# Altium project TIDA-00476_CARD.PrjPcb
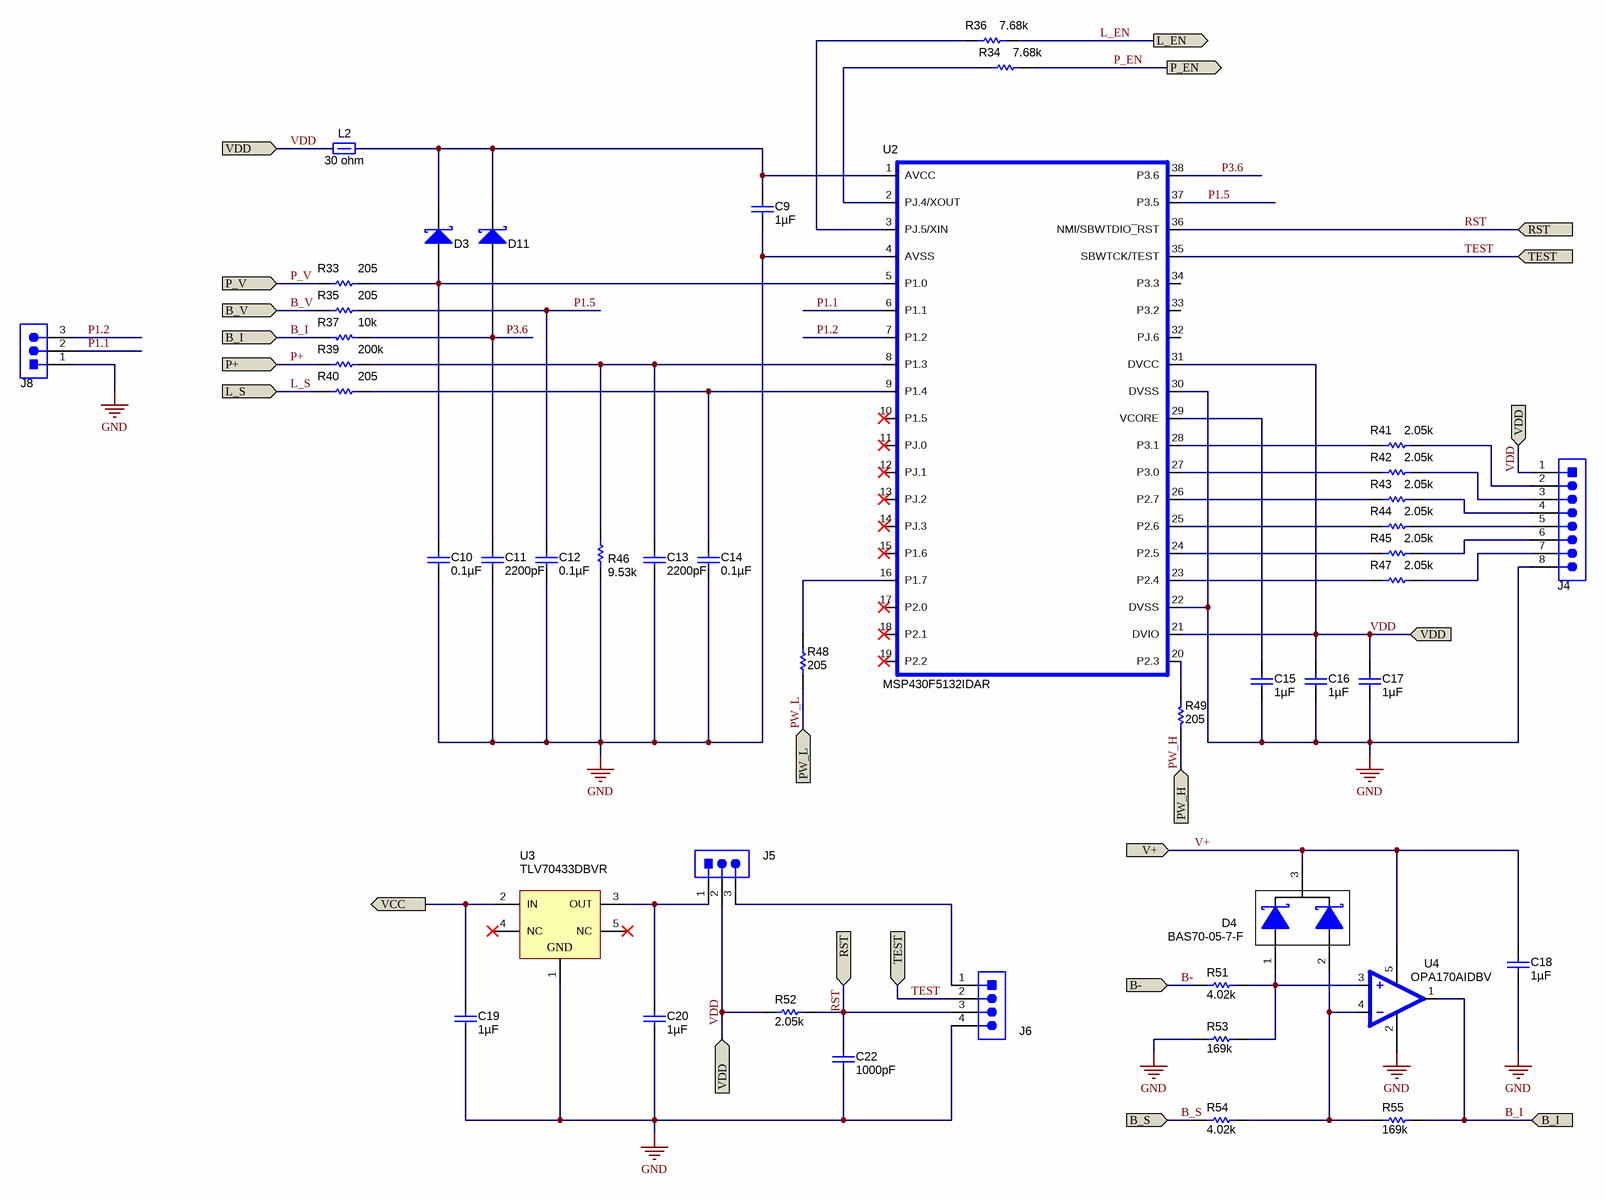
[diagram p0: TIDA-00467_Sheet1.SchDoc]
TechSupport: http://www.ti.com/support; SCH_Rev: E1; PRJ_Title: Versatile Bi-Directional Power Converter; PRJ_Number: TIDA-00476; PRJ_Engineer: Ramkumar S; PRJ_Customer: Public Release; PCB_Rev: E1; PCB_Layout: Manjunatha T N; CopyrightYear: 2015
3 sheets, 133 parts. Net scope: flat (ports and power ports of the same name join across sheets).
Board file: TIDA-00476_E1.PcbDoc
Sheets:
  TIDA-00467_Sheet1.SchDoc
  TIDA-00476_Sheet2.SchDoc
  Hardware.SchDoc

## Sheet TIDA-00467_Sheet1.SchDoc
size 431 x 279 mm; Date: Not shown in title block; ApprovedBy: Not shown in title block; CheckedBy: Not shown in title block; Author: Not shown in title block; CompanyName: Not shown in title block; Engineer: Not shown in title block; Organization: Not shown in title block; Address1: Not shown in title block; Address2: Not shown in title block; Address3: Not shown in title block; Address4: Not shown in title block; DocumentNumber: 1; Revision: Use project parameter SCH_Rev; SheetNumber: 1; SheetTotal: 3; PageSetup: Record=PageOptions¦CenterHorizontal=True¦CenterVertical=True¦PrintScale=1.00¦XCorrection=1.00¦YCorrection=1.00¦PrintKind=0¦BorderSize=5000000¦LeftOffset=0¦BottomOffset=0¦Orientation=2¦PaperLength=1000¦PaperWidth=1000¦Scale=100¦PaperSource=15¦PrintQuality=600¦MediaType=1¦DitherType=10¦PaperKind=Letter¦PrintScaleMode=1

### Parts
C9  ValueDisplayed: 1µF  [0805_HV]  (hidden comment: 08055C105KAT2A)
C10  ValueDisplayed: 0.1µF  [0805_HV]  (hidden comment: 08053C104KAT2A)
C11  ValueDisplayed: 2200pF  [0805_HV]  (hidden comment: 08055C222KAT2A)
C12  ValueDisplayed: 0.1µF  [0805_HV]  (hidden comment: 08053C104KAT2A)
C13  ValueDisplayed: 2200pF  [0805_HV]  (hidden comment: 08055C222KAT2A)
C14  ValueDisplayed: 0.1µF  [0805_HV]  (hidden comment: 08053C104KAT2A)
C15  ValueDisplayed: 1µF  [0805_HV]  (hidden comment: 08055C105KAT2A)
C16  ValueDisplayed: 1µF  [0805_HV]  (hidden comment: 08055C105KAT2A)
C17  ValueDisplayed: 1µF  [0805_HV]  (hidden comment: 08055C105KAT2A)
C18  ValueDisplayed: 1µF  [0805_HV]  (hidden comment: 08055C105KAT2A)
C19  ValueDisplayed: 1µF  [0805_HV]  (hidden comment: 08055C105KAT2A)
C20  ValueDisplayed: 1µF  [0805_HV]  (hidden comment: 08055C105KAT2A)
C22  ValueDisplayed: 1000pF  [0805_HV]  (hidden comment: 08055C102KAT2A)
D3  BAS 52-02V H6327  [SOD-523]  (value not drawn)
D4  BAS70-05-7-F  [SOT-23]
D11  BAS 52-02V H6327  [SOD-523]  (value not drawn)
J4  TSW-108-07-G-S  [TSW-108-07-G-S]  (value not drawn)
J5  5-146278-3  [TE_5-146278-3]  (value not drawn)
J6  5-146278-4  [TE_5-146278-4]  (value not drawn)
J8  5-146278-3  [TE_5-146278-3]  (value not drawn)
L2  value 30 ohm  [0805_HV]  (hidden comment: MMZ2012R300A)
R33  value 205  [0805_HV]  (hidden comment: CRCW0805205RFKEA)
R34  ValueDisplayed: 7.68k  [0805_HV]  (hidden comment: CRCW08057K68FKEA)
R35  value 205  [0805_HV]  (hidden comment: CRCW0805205RFKEA)
R36  ValueDisplayed: 7.68k  [0805_HV]  (hidden comment: CRCW08057K68FKEA)
R37  value 10k  [0805_HV]  (hidden comment: CRCW080510K0JNEA)
R39  ValueDisplayed: 200k  [0805_HV]  (hidden comment: CRCW0805200KFKEA)
R40  value 205  [0805_HV]  (hidden comment: CRCW0805205RFKEA)
R41  value 2.05k  [0805_HV]  (hidden comment: CRCW08052K05FKEA)
R42  value 2.05k  [0805_HV]  (hidden comment: CRCW08052K05FKEA)
R43  value 2.05k  [0805_HV]  (hidden comment: CRCW08052K05FKEA)
R44  value 2.05k  [0805_HV]  (hidden comment: CRCW08052K05FKEA)
R45  value 2.05k  [0805_HV]  (hidden comment: CRCW08052K05FKEA)
R46  ValueDisplayed: 9.53k  [0805_HV]  (hidden comment: CRCW08059K53FKEA)
R47  value 2.05k  [0805_HV]  (hidden comment: CRCW08052K05FKEA)
R48  value 205  [0805_HV]  (hidden comment: CRCW0805205RFKEA)
R49  value 205  [0805_HV]  (hidden comment: CRCW0805205RFKEA)
R51  ValueDisplayed: 4.02k  [0805_HV]  (hidden comment: RT0805BRD074K02L)
R52  value 2.05k  [0805_HV]  (hidden comment: CRCW08052K05FKEA)
R53  ValueDisplayed: 169k  [0805_HV]  (hidden comment: RT0805BRD07169KL)
R54  ValueDisplayed: 4.02k  [0805_HV]  (hidden comment: RT0805BRD074K02L)
R55  ValueDisplayed: 169k  [0805_HV]  (hidden comment: RT0805BRD07169KL)
U2  MSP430F5132IDAR  [DA_38P]
U3  TLV70433DBVR  [DBV0005A_N]
U4  OPA170AIDBV  [SOT23-5P]

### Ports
B- (in), B_I (in), B_S (in), B_V (in), L_EN (out), L_S (in), P+ (in), P_EN (out), P_V (in), PW_H (in), PW_L (in), RST (in), TEST (in), V+, VCC, VDD, VDD (in)

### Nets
GND: C9.2 C10.2 C11.2 C12.2 C13.2 C14.2 C15.2 C16.2 C17.2 C18.2 C19.2 C20.2 C22.2 J4.8 J6.4 J8.1 R46.1 R53.1 U2.4(AVSS) U2.22(DVSS) U2.30(DVSS) U3.1(GND) U4.2(V-)
B-: R51.1 ; port B-
B_I: R37.2 R55.2 U4.1(OUT) ; port B_I
B_S: R54.1 ; port B_S
B_V: R35.1 ; port B_V
L_EN: R36.1 ; port L_EN
L_S: R40.1 ; port L_S
P1.1: J8.2 U2.6(P1.1)
P1.2: J8.3 U2.7(P1.2)
P1.5: C12.1 R35.2 U2.37(P3.5)
P3.6: C11.1 D11.2(A) R37.1 U2.38(P3.6)
P+: R39.1 ; port P+
P_EN: R34.1 ; port P_EN
P_V: R33.1 ; port P_V
PW_H: R49.1 ; port PW_H
PW_L: R48.1 ; port PW_L
RST: C22.1 J6.3 R52.2 U2.36(NMI/SBWTDIO~{_}RST) ; port RST
TEST: J6.2 U2.35(SBWTCK/TEST) ; port TEST
V+: C18.1 D4.3(K) U4.5(V+) ; port V+
VCC: C19.1 U3.2(IN) ; port VCC
VDD: C16.1 C17.1 J4.1 J5.2 L2.1 R52.1 U2.21(DVIO) U2.31(DVCC) ; port VDD
NetC9_1: C9.1 D3.1(K) D11.1(K) L2.2 U2.1(AVCC)
NetC10_1: C10.1 D3.2(A) R33.2 U2.5(P1.0)
NetC13_1: C13.1 R39.2 R46.2 U2.8(P1.3)
NetC14_1: C14.1 R40.2 U2.9(P1.4)
NetC15_1: C15.1 U2.29(VCORE)
NetC20_1: C20.1 J5.1 U3.3(OUT)
NetD4_1: D4.1(A) R51.2 R53.2 U4.3
NetD4_2: D4.2(A) R54.2 R55.1 U4.4
NetJ4_2: J4.2 R41.2
NetJ4_3: J4.3 R42.2
NetJ4_4: J4.4 R43.2
NetJ4_5: J4.5 R44.2
NetJ4_6: J4.6 R45.2
NetJ4_7: J4.7 R47.2
NetJ5_3: J5.3 J6.1
NetR34_2: R34.2 U2.2(PJ.4/XOUT)
NetR36_2: R36.2 U2.3(PJ.5/XIN)
NetR41_1: R41.1 U2.28(P3.1)
NetR42_1: R42.1 U2.27(P3.0)
NetR43_1: R43.1 U2.26(P2.7)
NetR44_1: R44.1 U2.25(P2.6)
NetR45_1: R45.1 U2.24(P2.5)
NetR47_1: R47.1 U2.23(P2.4)
NetR48_2: R48.2 U2.16(P1.7)
NetR49_2: R49.2 U2.20(P2.3)

Not connected (* = marked no-connect by the designer): U2 10(P1.5)* 11(PJ.0)* 12(PJ.1)* 13(PJ.2)* 14(PJ.3)* 15(P1.6)* 17(P2.0)* 18(P2.1)* 19(P2.2)* 32(PJ.6) 33(P3.2) 34(P3.3); U3 4(NC)* 5(NC)*

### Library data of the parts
C9 C15-C20 = 08055C105KAT2A: CAP, CERM, 1uF, 50V, +/-10%, X7R, 0805; Manufacturer: AVX; Polarized: N; CompType: Capacitor; U/M: EA; Cap_F: 0.000001; Tolerance_%: 10; Value1: Unknown; VDC_V: 50; TaMin_C: -55; TaMax_C: 125; Cap_Case: 0805
C10 C12 C14 = 08053C104KAT2A: CAP, CERM, 0.1uF, 25V, +/-10%, X7R, 0805; Manufacturer: AVX; Polarized: N; CompType: Capacitor; U/M: EA; Cap_F: 0.0000001; Tolerance_%: 10; ESR_Ohm: 0.28; Value1: 0.28 ohm; VDC_V: 25; TaMin_C: -55; TaMax_C: 125; Cap_Case: 0805
C11 C13 = 08055C222KAT2A: CAP, CERM, 2200 pF, 50 V, +/- 10%, X7R, 0805; Manufacturer: AVX; Polarized: N; CompType: Capacitor; Value: 2200pF; U/M: EA; Cap_F: 0.0000000022; Tolerance_%: 10; ESR_ohm: 0.183; Value1: 0.183 ohm; VDC_V: 50; Value2: 50V; TaMin_C: -55; TaMax_C: 125; Cap_Case: 0805
C22 = 08055C102KAT2A: CAP, CERM, 1000 pF, 50 V, +/- 10%, X7R, 0805; Manufacturer: AVX; Polarized: N; CompType: Capacitor; Value: 1000pF; U/M: EA; Cap_F: 0.000000001; Tolerance_%: 10; ESR_ohm: 0.29; Value1: 0.29 ohm; VDC_V: 50; Value2: 50V; TaMin_C: -55; TaMax_C: 125; Cap_Case: 0805
D3 D11 = BAS 52-02V H6327: Diode, Schottky, 45 V, 0.75 A, SOD-523; Manufacturer: Infineon Technologies; U/M: EA; Vf_V: 0.6; Value: 45V; Value1: 0.75A; Value2: 0.6V; Io_A: 0.75; Vr_V: 45; TJmax_C: 150
D4 = BAS70-05-7-F: Diode, Schottky, 70 V, 0.07 A, SOT-23; Manufacturer: Diodes Inc.; SymbolCreator: a0412235; U/M: EA; Vf_V: 1.7; Value: 70V; Value1: 0.07A; Value2: 1.7V; Io_A: 0.07; Vr_V: 70
J4 = TSW-108-07-G-S: Header, TH, 100mil, 8x1, Gold plated, 230 mil above insulator; Manufacturer: Samtec; SymbolCreator: a0411947; U/M: EA
J5 J8 = 5-146278-3: Header, 100mil, 3x1, Tin, TH; Manufacturer: TE Connectivity; SymbolCreator: a0799628; U/M: EA
J6 = 5-146278-4: Header, 100mil, 4x1, Tin, TH; Manufacturer: TE Connectivity; SymbolCreator: a0412235; U/M: EA
L2 = MMZ2012R300A: Ferrite Bead, 30 ohm @ 100MHz, 1.5A, 0805; Manufacturer: TDK; Imax_A: 1.5; DCR_ohm: 0.05; Value1: 0.05 ohm; ZTyp@100MHz_Ohm: 30
R33 R35 R40 R48 R49 = CRCW0805205RFKEA: RES, 205 ohm, 1%, 0.125W, 0805; Manufacturer: Vishay-Dale; CompType: Resistor; Value_Code: 205R; Tolerance_%: 1; Power_W: 0.125; VDC_V: 150; TempCo: 100 ppm/C; EIA_Code: E96; U/M: EA
R34 R36 = CRCW08057K68FKEA: RES, 7.68 k, 1%, 0.125 W, 0805; Manufacturer: Vishay-Dale; CompType: Resistor; Value: 7.68k; Res_ohm: 7680; Value_Code: 7k68; Tolerance_%: 1; Power_W: 0.125; Value2: 0.125W; VDC_V: 150; TempCo: 100 ppm/C; EIA_Code: E96; U/M: EA
R37 = CRCW080510K0JNEA: RES, 10k ohm, 5%, 0.125W, 0805; Manufacturer: Vishay-Dale; CompType: Resistor; Res_ohm: 10000; Value_Code: 10k0; Tolerance_%: 5; Power_W: 0.125; VDC_V: 150; TempCo: 200 ppm/C; EIA_Code: E24; U/M: EA
R39 = CRCW0805200KFKEA: RES, 200 k, 1%, 0.125 W, 0805; Manufacturer: Vishay-Dale; CompType: Resistor; Value: 200k; Res_ohm: 200000; Tolerance_%: 1; Power_W: 0.125; Value2: 0.125W; VDC_V: 150; TempCo: 100 ppm/C; EIA_Code: E96; U/M: EA
R41-R45 R47 R52 = CRCW08052K05FKEA: RES, 2.05k ohm, 1%, 0.125W, 0805; Manufacturer: Vishay-Dale; CompType: Resistor; Res_ohm: 2050; Value_Code: 2k05; Tolerance_%: 1; Power_W: 0.125; VDC_V: 150; TempCo: 100 ppm/C; EIA_Code: E96; U/M: EA
R46 = CRCW08059K53FKEA: RES, 9.53 k, 1%, 0.125 W, 0805; Manufacturer: Vishay-Dale; CompType: Resistor; Value: 9.53k; Res_ohm: 9530; Value_Code: 9k53; Tolerance_%: 1; Power_W: 0.125; Value2: 0.125W; VDC_V: 150; TempCo: 100 ppm/C; EIA_Code: E96; U/M: EA
R51 R54 = RT0805BRD074K02L: RES, 4.02 k, 0.1%, 0.125 W, 0805; Manufacturer: Yageo America; CompType: Resistor; Value: 4.02k; Res_ohm: 4020; Value_Code: 4k02; Tolerance_%: 0.1; Power_W: 0.125; Value2: 0.125W; VDC_V: 150; TempCo: 25 ppm/C; EIA_Code: E192; U/M: EA
R53 R55 = RT0805BRD07169KL: RES, 169 k, 0.1%, 0.125 W, 0805; Manufacturer: Yageo America; CompType: Resistor; Value: 169k; Res_ohm: 169000; Tolerance_%: 0.1; Power_W: 0.125; Value2: 0.125W; VDC_V: 150; TempCo: 25 ppm/C; EIA_Code: E192; U/M: EA
U2 = MSP430F5132IDAR: IC, MIXED SIGNAL MICROCONTROLLER; Manufacturer: TI; Alternate Manufacturer: None; Area: 330000
U3 = TLV70433DBVR: Single Output LDO, 150 mA, Fixed 3.3 V Output, 2.5 to 24 V Input, with Ultra-Low IQ, 5-pin SOT-23 (DBV), -40 to 125 degC, Green (RoHS & no Sb/Br); Manufacturer: Texas Instruments; Alternate Manufacturer: None; Alternate PartNumber: Equivalent; Accuracy(%): 2; Fixed Output Options(V): 3.3; Iout(Max)(A): 0.15; Iq(Typ)(mA): 0.003; SubFamily: Single Channel LDO; Vdo(Typ)(mV): 400; Vin(Max)(V): 24; Vin(Min)(V): 2.5
U4 = OPA170AIDBV: IC, 36V, Single-Supply, Op Amp; Manufacturer: TI; Alternate Manufacturer: None; Area: 8700

## Sheet TIDA-00476_Sheet2.SchDoc
size 431 x 279 mm; Date: Not shown in title block; ApprovedBy: Not shown in title block; CheckedBy: Not shown in title block; Author: Not shown in title block; CompanyName: Not shown in title block; Engineer: Not shown in title block; Organization: Not shown in title block; Address1: Not shown in title block; Address2: Not shown in title block; Address3: Not shown in title block; Address4: Not shown in title block; DocumentNumber: 2; Revision: Use project parameter SCH_Rev; SheetNumber: 2; SheetTotal: 3; PageSetup: Record=PageOptions¦CenterHorizontal=True¦CenterVertical=True¦PrintScale=0.64¦XCorrection=1.00¦YCorrection=1.00¦PrintKind=0¦BorderSize=5000000¦LeftOffset=0¦BottomOffset=0¦Orientation=2¦PaperLength=1000¦PaperWidth=1000¦Scale=100¦PaperSource=15¦PrintQuality=600¦MediaType=1¦DitherType=10¦PrintScaleMode=1¦PaperKind=Letter
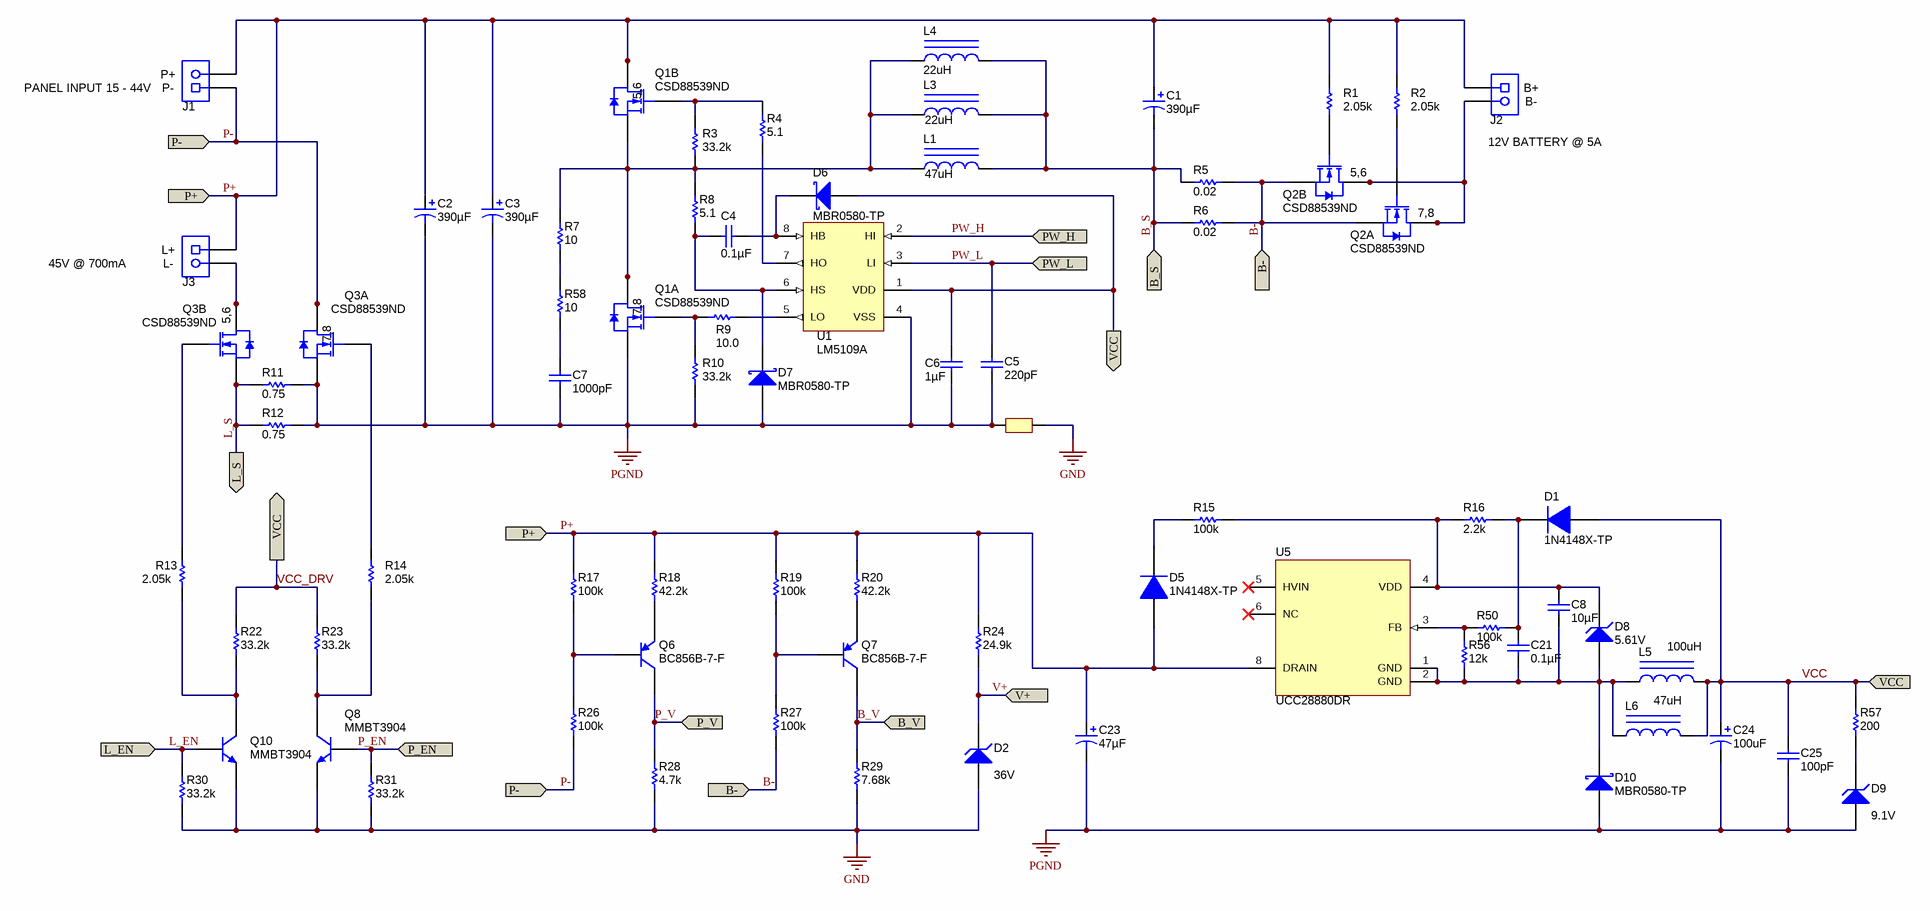
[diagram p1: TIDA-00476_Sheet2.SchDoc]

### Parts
C1  ValueDisplayed: 390µF  [KZN_1000x2000]  (hidden comment: EKYB630ELL391MJ30S)
C2  ValueDisplayed: 390µF  [KZN_1000x2000]  (hidden comment: EKYB630ELL391MJ30S)
C3  ValueDisplayed: 390µF  [KZN_1000x2000]  (hidden comment: EKYB630ELL391MJ30S)
C4  ValueDisplayed: 0.1µF  [0805_HV]  (hidden comment: 08053C104KAT2A)
C5  ValueDisplayed: 220pF  [0805_HV]  (hidden comment: GRM2165C2A221JA01D)
C6  ValueDisplayed: 1µF  [0805_HV]  (hidden comment: 08055C105KAT2A)
C7  ValueDisplayed: 1000pF  [0805_HV]  (hidden comment: GRM2195C2A102JA01D)
C8  ValueDisplayed: 10µF  [0603]  (hidden comment: C1608X5R1A106M)
C21  ValueDisplayed: 0.1µF  [0603]  (hidden comment: 0603YC104JAT2A)
C23  ValueDisplayed: 47µF  [ZLJ_500x1100]  (hidden comment: 35ZLJ47MTA5X11)
C24  ValueDisplayed: 100uF  [ZLJ_500x1100]  (hidden comment: 16PX100MEFCTA5X11)
C25  ValueDisplayed: 100pF  [0603]  (hidden comment: 06033C101KAT2A)
D1  1N4148X-TP  [SOD-523]
D2  value 36V  [SOD-123]  (hidden comment: MMSZ4715-V)
D5  1N4148X-TP  [SOD-523]
D6  MBR0580-TP  [SOD-123]
D7  MBR0580-TP  [SOD-123]
D8  5.61V  [SOD-523]
D9  value 9.1V  [SOD-123]  (hidden comment: MMSZ4696-V)
D10  MBR0580-TP  [SOD-123]
J1  282841-2  [TEC_282841-2]  (value not drawn)
J2  282841-2  [TEC_282841-2]  (value not drawn)
J3  282841-2  [TEC_282841-2]  (value not drawn)
L1  value 47uH  [WE-HCB_1890]  (hidden comment: 74435574700)
L3  value 22uH  [mss1278]  (hidden comment: MSS1278-223MLB)
L4  22uH  [WE-HCB_1890]
L5  100uH  [SRN3015]
L6  47uH  [SRN3015]
NT1  Net-Tie  [Net-Tie_20milWide_60milLong]  (value not drawn)  (net tie, no BOM)
Q1  CSD88539ND  [SO-8L]  (parts A,B of 2)
Q2  CSD88539ND  [SO-8L]  (parts A,B of 2)
Q3  CSD88539ND  [SO-8L]  (parts A,B of 2)
Q6  BC856B-7-F  [SOT-23]
Q7  BC856B-7-F  [SOT-23]
Q8  MMBT3904  [SOT-23L]
Q10  MMBT3904  [SOT-23L]
R1  value 2.05k  [0805_HV]  (hidden comment: CRCW08052K05FKEA)
R2  value 2.05k  [0805_HV]  (hidden comment: CRCW08052K05FKEA)
R3  value 33.2k  [0805_HV]  (hidden comment: CRCW080533K2FKEA)
R4  ValueDisplayed: 5.1  [0805_HV]  (hidden comment: RC0805JR-075R1L)
R5  ValueDisplayed: 0.02  [1206]  (hidden comment: CSR1206FK20L0)
R6  ValueDisplayed: 0.02  [1206]  (hidden comment: CSR1206FK20L0)
R7  ValueDisplayed: 10  [1206]  (hidden comment: CRCW120610R0JNEA)
R8  ValueDisplayed: 5.1  [0603]  (hidden comment: CRCW06035R10JNEA)
R9  value 10.0  [0805_HV]  (hidden comment: CRCW080510R0FKEA)
R10  value 33.2k  [0805_HV]  (hidden comment: CRCW080533K2FKEA)
R11  ValueDisplayed: 0.75  [1206]  (hidden comment: CSR1206FKR750)
R12  ValueDisplayed: 0.75  [1206]  (hidden comment: CSR1206FKR750)
R13  value 2.05k  [0805_HV]  (hidden comment: CRCW08052K05FKEA)
R14  value 2.05k  [0805_HV]  (hidden comment: CRCW08052K05FKEA)
R15  ValueDisplayed: 100k  [0603]  (hidden comment: CRCW0603100KJNEA)
R16  ValueDisplayed: 2.2k  [0603]  (hidden comment: CRCW06032K20JNEA)
R17  value 100k  [0805_HV]  (hidden comment: CRCW0805100KFKEA)
R18  ValueDisplayed: 42.2k  [0805_HV]  (hidden comment: CRCW080542K2FKEA)
R19  value 100k  [0805_HV]  (hidden comment: CRCW0805100KFKEA)
R20  ValueDisplayed: 42.2k  [0805_HV]  (hidden comment: CRCW080542K2FKEA)
R22  value 33.2k  [0805_HV]  (hidden comment: CRCW080533K2FKEA)
R23  value 33.2k  [0805_HV]  (hidden comment: CRCW080533K2FKEA)
R24  ValueDisplayed: 24.9k  [0805_HV]  (hidden comment: ERJ-6ENF2492V)
R26  value 100k  [0805_HV]  (hidden comment: CRCW0805100KFKEA)
R27  value 100k  [0805_HV]  (hidden comment: CRCW0805100KFKEA)
R28  ValueDisplayed: 4.7k  [0805_HV]  (hidden comment: CRCW08054K70JNEA)
R29  ValueDisplayed: 7.68k  [0805_HV]  (hidden comment: CRCW08057K68FKEA)
R30  value 33.2k  [0805_HV]  (hidden comment: CRCW080533K2FKEA)
R31  value 33.2k  [0805_HV]  (hidden comment: CRCW080533K2FKEA)
R50  ValueDisplayed: 100k  [0603]  (hidden comment: CRCW0603100KJNEA)
R56  ValueDisplayed: 12k  [0603]  (hidden comment: CRCW060312K0JNEA)
R57  ValueDisplayed: 200  [0603]  (hidden comment: CRCW0603200RJNEA)
R58  ValueDisplayed: 10  [1206]  (hidden comment: CRCW120610R0JNEA)
U1  LM5109A  [M08A_N]
U5  UCC28880DR  [D0007A_N]

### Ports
B- (in), B_S (in), B_V (in), L_EN (in), L_S (out), P+ (in), P- (in), P_EN (in), P_V (in), PW_H, PW_L, V+, VCC

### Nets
GND: D2.2(A) NT1.1 Q8.2(E) Q10.2(E) R28.1 R29.1 R30.1 R31.1
PGND: C2.2(-) C3.2(-) C5.2 C6.2 C7.2 C23.2(-) C24.2(-) C25.2 D7.2(A) D9.2(A) D10.2(A) NT1.2 Q1.1(S) Q3.1(S) R10.1 R11.2 R12.2 U1.4(VSS)
B-: Q2.1(S) Q2.3(S) R5.2 R6.2 R27.1 ; port B-
B_S: C1.2(-) L1.2 L3.2 L4.2 R5.1 R6.1 ; port B_S
B_V: Q7.3(C) R29.2 ; port B_V
L_EN: Q10.1(B) R30.2 ; port L_EN
L_S: Q3.3(S) R11.1 R12.1 ; port L_S
P+: C1.1(+) C2.1(+) C3.1(+) C23.1(+) D5.2(A) J1.2 J2.1 J3.1 Q1.5(D) Q1.6(D) R1.2 R2.2 R17.2 R18.2 R19.2 R20.2 R24.2 U5.8(DRAIN) ; port P+
P-: J1.1 Q3.7(D) Q3.8(D) R26.1 ; port P-
P_EN: Q8.1(B) R31.2 ; port P_EN
P_V: Q6.3(C) R28.2 ; port P_V
PW_H: U1.2(HI) ; port PW_H
PW_L: C5.1 U1.3(LI) ; port PW_L
V+: D2.1(K) R24.1 ; port V+
VCC: C6.1 C24.1(+) C25.1 D1.2(A) D6.2(A) L5.2 L6.2 R22.2 R23.2 R57.2 U1.1(VDD) ; port VCC  [also labelled VCC_DRV]
NetC4_1: C4.1 D6.1(K) U1.8(HB)
NetC4_2: C4.2 D7.1(K) R8.1 U1.6(HS)
NetC7_1: C7.1 R58.1
NetC8_1: C8.1 D8.1(K) R15.1 R16.1 U5.4(VDD)
NetC8_2: C8.2 C21.2 D8.2(A) D10.1(K) L5.1 L6.1 R56.1 U5.1(GND) U5.2(GND)
NetC21_1: C21.1 D1.1(K) R16.2 R50.1
NetD5_1: D5.1(K) R15.2
NetD9_1: D9.1(K) R57.1
NetJ2_2: J2.2 Q2.5(D) Q2.6(D) Q2.7(D) Q2.8(D)
NetJ3_2: J3.2 Q3.5(D) Q3.6(D)
NetL1_1: L1.1 L3.1 L4.1 Q1.3(S) Q1.7(D) Q1.8(D) R3.1 R7.2 R8.2
NetQ1_2: Q1.2(G) R9.1 R10.2
NetQ1_4: Q1.4(G) R3.2 R4.2
NetQ2_2: Q2.2(G) R2.1
NetQ2_4: Q2.4(G) R1.1
NetQ3_2: Q3.2(G) R14.2
NetQ3_4: Q3.4(G) R13.2
NetQ6_1: Q6.1(B) R17.1 R26.2
NetQ6_2: Q6.2(E) R18.1
NetQ7_1: Q7.1(B) R19.1 R27.2
NetQ7_2: Q7.2(E) R20.1
NetQ8_3: Q8.3(C) R14.1 R23.1
NetQ10_3: Q10.3(C) R13.1 R22.1
NetR4_1: R4.1 U1.7(HO)
NetR7_1: R7.1 R58.2
NetR9_2: R9.2 U1.5(LO)
NetR50_2: R50.2 R56.2 U5.3(FB)

Not connected (* = marked no-connect by the designer): U5 5(HVIN)* 6(NC)*

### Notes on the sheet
- PANEL INPUT 15 - 44V
- (near J1) P+
- (near J1) P-
- (near J2) B-
- (near J2) B+
- (near J2) 12V BATTERY @ 5A
- 45V @ 700mA
- (near J3) L-
- (near J3) L+

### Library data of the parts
C1 = EKZN350ELL471MJ20S: CAP, AL,390 µF, 63 V, +/- 20%, 0.043 ohm, TH; Manufacturer: Chemi-Con; Polarized: Y; CompType: Capacitor; Value: 390uF; U/M: EA; Cap_F: 0.00039; Tolerance_%: 20; Value1: 0.04 ohm; VDC_V: 63; Value2: 63V; ESR_ohm: 0.04; IRMS_A: 1.78; TaMin_C: -40; TaMax_C: 105; Cap_Case: 10x30mm
C2 C3 = EKZN350ELL471MJ20S: CAP, AL, 470 µF, 35 V, +/- 20%, 0.028 ohm, TH; Manufacturer: Chemi-Con; Polarized: Y; CompType: Capacitor; Value: 390uF; U/M: EA; Cap_F: 0.00039; Tolerance_%: 20; Value1: 0.04 ohm; VDC_V: 63; Value2: 63V; ESR_ohm: 0.04; IRMS_A: 1.78; TaMin_C: -40; TaMax_C: 105; Cap_Case: 10x30mm
C4 = 08053C104KAT2A: as C10 on sheet TIDA-00467_Sheet1
C5 = GRM2165C2A221JA01D: CAP, CERM, 220 pF, 100 V, +/- 5%, C0G/NP0, 0805; Manufacturer: MuRata; Polarized: N; CompType: Capacitor; Value: 220pF; U/M: EA; Cap_F: 0.00000000022; Tolerance_%: 5; Value1: Unknown; VDC_V: 100; Value2: 100V; TaMin_C: -55; TaMax_C: 125; Cap_Case: 0805
C6 = 08055C105KAT2A: as C9 on sheet TIDA-00467_Sheet1
C7 = GRM2195C2A102JA01D: CAP, CERM, 1000 pF, 100 V, +/- 5%, C0G/NP0, 0805; Manufacturer: MuRata; Polarized: N; CompType: Capacitor; Value: 1000pF; U/M: EA; Cap_F: 0.000000001; Tolerance_%: 5; Value1: Unknown; VDC_V: 100; Value2: 100V; TaMin_C: -55; TaMax_C: 125; Cap_Case: 0805
C8 = C1608X5R1A106M: CAP, CERM, 10 µF, 10 V, +/- 20%, X5R, 0603; Manufacturer: TDK; Polarized: N; CompType: Capacitor; Value: 10uF; U/M: EA; Cap_F: 0.00001; Tolerance_%: 20; ESR_ohm: 0.0078; Value1: 0.0078 ohm; VDC_V: 10; Value2: 10V; IRMS_A: 1.85; TaMin_C: -55; TaMax_C: 85
C21 = 0603YC104JAT2A: CAP, CERM, 0.1 µF, 16 V, +/- 5%, X7R, 0603; Manufacturer: AVX; Polarized: N; CompType: Capacitor; Value: 0.1uF; U/M: EA; Cap_F: 0.0000001; Tolerance_%: 5; ESR_ohm: 0.039; Value1: 0.039 ohm; VDC_V: 16; Value2: 16V; TaMin_C: -55; TaMax_C: 125
C23 = 35ZLJ47MTA5X11: CAP, AL, 47 µF, 35 V, +/- 20%, 0.4 ohm, TH; Manufacturer: Rubycon; Polarized: Y; CompType: Capacitor; Value: 47uF; U/M: EA; Cap_F: 0.000047; Tolerance_%: 20; Value1: 0.4 ohm; VDC_V: 35; Value2: 35V; ESR_ohm: 0.4; IRMS_A: 0.45; TaMin_C: -40; TaMax_C: 105; Cap_Case: 5x11mm
C24 = 35ZLJ47MTA5X11: CAP, AL, 100 µF, 16 V, +/- 20%, 0.4 ohm, TH; Manufacturer: Rubycon; Polarized: Y; CompType: Capacitor; Value: 100uF; U/M: EA; Cap_F: 0.000047; Tolerance_%: 20; Value1: 0.4 ohm; VDC_V: 16; Value2: 16V; ESR_ohm: 0.4; IRMS_A: 0.45; TaMin_C: -40; TaMax_C: 105; Cap_Case: 5x11mm
C25 = 06033C101KAT2A: CAP, CERM, 100 pF, 25 V, +/- 10%, X7R, 0603; Manufacturer: AVX; Polarized: N; CompType: Capacitor; Value: 100pF; U/M: EA; Cap_F: 0.0000000001; Tolerance_%: 10; Value1: Unknown; VDC_V: 25; Value2: 25V; TaMin_C: -55; TaMax_C: 125
D1 D5 = 1N4148X-TP: Diode, Switching, 75 V, 0.3 A, SOD-523; Manufacturer: Micro Commercial Components; U/M: EA; Vf_V: 1.25; Value: 75V; Value1: 0.3A; Value2: 1.25V; Io_A: 0.3; Vr_V: 75; TJmax_C: 150
D2 = MMSZ4715-V: Diode, Zener, 36 V, 500 mW, SOD-123; Manufacturer: Vishay-Semiconductor; SymbolCreator: a0412235; U/M: EA; Power_W: 0.5; Vz_V: 36; Value1: 0.5W; RJA_CperW: 67
D6 D7 D10 = MBR0580-TP: Diode, Schottky, 80 V, 0.5 A, SOD-123; Manufacturer: Micro Commercial Components; U/M: EA; Vf_V: 0.8; Value: 80V; Value1: 0.5A; Value2: 0.8V; Io_A: 0.5; Vr_V: 80; TJmax_C: 150
D8 = MM5Z5V6ST1G: Diode, Zener, 5.61 V, 500 mW, SOD-523; Manufacturer: ON Semiconductor; SymbolCreator: a0412235; U/M: EA; Power_W: 0.5; Vz_V: 5.61; Value1: 0.5W; RJA_CperW: 250
D9 = MMSZ4696-V: Diode, Zener, 9.1 V, 500 mW, SOD-123; Manufacturer: Vishay-Semiconductor; SymbolCreator: a0412235; U/M: EA; Power_W: 0.5; Vz_V: 9.1; Value1: 0.5W; RJA_CperW: 67
J1-J3 = 282841-2: Terminal Block, 2x1, 5.08mm, TH; Manufacturer: TE Connectivity; SymbolCreator: a0412235; U/M: EA
L1 = 74435574700: Inductor, Shielded Drum Core, Ferrite, 47 µH, 6.8 A, 0.0335 ohm, SMD; Manufacturer: Wurth Elektronik; Ind_H: 47.0E-6; ValueDisplayed: 47µH; Imax_A: 6.8; Irms: 6.8A @ 50C rise; Isat: 7A @ 30% inductance drop; DCR_ohm: 0.0335; Value2: 6.8A
L3 = MSS1278-223MLB: Inductor, Shielded Drum Core, Ferrite, 22 µH, 4 A, 0.04 ohm, SMD; Manufacturer: Coilcraft; Ind_H: 22.0E-6; ValueDisplayed: 22µH; Imax_A: 4; Irms: 4A @ 40C rise; Isat: 7.24A @ 30% inductance drop; DCR_ohm: 0.04; Value2: 4A
L4 = 74435572200: Inductor, Shielded Drum Core, Ferrite, 22 µH, 11 A, 0.0146 ohm, SMD; Manufacturer: Wurth Elektronik; Ind_H: 22.0E-6; ValueDisplayed: 22µH; Imax_A: 11; Irms: 11A @ 50C rise; Isat: 11A @ 30% inductance drop; DCR_ohm: 0.0146; Value2: 11A
L5 = SRN3015-1R0Y: Inductor, Drum Core, Ferrite, 100 µH, 0.4 A, 1.596 ohm, SMD; PartNumber: SRN4018-101M; Manufacturer: Bourns; Ind_H: 1.0E-4; ValueDisplayed: 100µH; Imax_A: 0.4; DCR_ohm: 0.048; Value2: 0.4A
L6 = SRN3015-1R0Y: Inductor, Drum Core, Ferrite, 47 µH, 0.4 A, 1.4 ohm, SMD; PartNumber: SRN3015-470M; Manufacturer: Bourns; Ind_H: 47E-6; Imax_A: 2.35; DCR_ohm: 0.048; Value1: 1.4Ohm; Value2: 0.4A
NT1 = Net-Tie: Single point connection between nets.; SymbolCreator: codlsc
Q1-Q3 = CSD88539ND: MOSFET, N-CH, 60V, 6.3A, SO-8; Manufacturer: Texas Instruments; Alternate Manufacturer: None; U/M: EA; ChType: N; VdsMax_V: 60; Value1: ? ohm; Value2: 7.2 nC; QgTyp_nC: 7.2; Vgs_V: 20; IdsMax_A: 6.3
Q6 Q7 = BC856B-7-F, Diodes Inc.: Transistor, PNP, 65 V, 0.1 A, SOT-23; CompType: BJT; PNP: 1; NPN: 0; Vceo_V: 65; Vcesat1_V: 0.075; Value: 65 V; IcRated_A: 0.1; Value1: 0.1 A; HfeMax: 330; TaMin_C: -65; TaMax_C: 150; U/M: EA
Q8 Q10 = MMBT3904, Fairchild Semiconductor: Transistor, NPN, 40V, 0.2A, SOT-23; CompType: BJT; PNP: 0; NPN: 1; Vceo_V: 40; Vcesat1_V: 0.2; Value: 0.2V; HfeMax: 300; TaMin_C: -55; TaMax_C: 150; U/M: EA
R1 R2 R13 R14 = CRCW08052K05FKEA: as R41 on sheet TIDA-00467_Sheet1
R3 R10 R22 R23 R30 R31 = CRCW080533K2FKEA: RES, 33.2k ohm, 1%, 0.125W, 0805; Manufacturer: Vishay-Dale; CompType: Resistor; Res_ohm: 33200; Value_Code: 33k2; Tolerance_%: 1; Power_W: 0.125; VDC_V: 150; TempCo: 100 ppm/C; EIA_Code: E96; U/M: EA
R4 = RC0805JR-075R1L: RES, 5.1, 5%, 0.125 W, 0805; Manufacturer: Yageo America; CompType: Resistor; Value: 5.1; Value_Code: 5R10; Tolerance_%: 5; Power_W: 0.125; Value2: 0.125W; VDC_V: 150; TempCo: 200 ppm/C; EIA_Code: E24; U/M: EA
R5 R6 = CSR1206FK20L0: RES, 0.02, 1%, 0.5 W, 1206; Manufacturer: Stackpole Electronics Inc; CompType: Resistor; Value: 0.02; Value_Code: R020; Tolerance_%: 1; Power_W: 0.5; Value2: 0.5W; TempCo: 100 ppm/C; EIA_Code: E96; U/M: EA
R7 R58 = CRCW120610R0JNEA: RES, 10, 5%, 0.25 W, 1206; Manufacturer: Vishay-Dale; CompType: Resistor; Value: 10; Value_Code: 10R0; Tolerance_%: 5; Power_W: 0.25; Value2: 0.25W; VDC_V: 200; TempCo: 200 ppm/C; EIA_Code: E24; U/M: EA
R8 = CRCW06035R10JNEA: RES, 5.1, 5%, 0.1 W, 0603; Manufacturer: Vishay-Dale; CompType: Resistor; Value: 5.1; Value_Code: 5R10; Tolerance_%: 5; Power_W: 0.1; Value2: 0.1W; VDC_V: 75; TempCo: 200 ppm/C; EIA_Code: E24; U/M: EA
R9 = CRCW080510R0FKEA: RES, 10.0 ohm, 1%, 0.125W, 0805; Manufacturer: Vishay-Dale; CompType: Resistor; Res_ohm: 10; Value_Code: 10R0; Tolerance_%: 1; Power_W: 0.125; VDC_V: 150; TempCo: 100 ppm/C; EIA_Code: E96; U/M: EA
R11 R12 = CSR1206FKR750: RES, 0.75, 1%, 0.5 W, 1206; Manufacturer: Stackpole Electronics Inc; CompType: Resistor; Value: 0.75; Value_Code: R750; Tolerance_%: 1; Power_W: 0.5; Value2: 0.5W; TempCo: 100 ppm/C; EIA_Code: E96; U/M: EA
R15 R50 = CRCW0603100KJNEA: RES, 100 k, 5%, 0.1 W, 0603; Manufacturer: Vishay-Dale; CompType: Resistor; Value: 100k; Res_ohm: 100000; Tolerance_%: 5; Power_W: 0.1; Value2: 0.1W; VDC_V: 75; TempCo: 200 ppm/C; EIA_Code: E24; U/M: EA
R16 = CRCW06032K20JNEA: RES, 2.2 k, 5%, 0.1 W, 0603; Manufacturer: Vishay-Dale; CompType: Resistor; Value: 2.2k; Res_ohm: 2200; Value_Code: 2k20; Tolerance_%: 5; Power_W: 0.1; Value2: 0.1W; VDC_V: 75; TempCo: 200 ppm/C; EIA_Code: E24; U/M: EA
R17 R19 R26 R27 = CRCW0805100KFKEA: RES, 100k ohm, 1%, 0.125W, 0805; Manufacturer: Vishay-Dale; CompType: Resistor; Res_ohm: 100000; Tolerance_%: 1; Power_W: 0.125; VDC_V: 150; TempCo: 100 ppm/C; EIA_Code: E96; U/M: EA
R18 R20 = CRCW080542K2FKEA: RES, 42.2 k, 1%, 0.125 W, 0805; Manufacturer: Vishay-Dale; CompType: Resistor; Value: 42.2k; Res_ohm: 42200; Value_Code: 42k2; Tolerance_%: 1; Power_W: 0.125; Value2: 0.125W; VDC_V: 150; TempCo: 100 ppm/C; EIA_Code: E96; U/M: EA
R24 = ERJ-6ENF2492V: RES, 24.9 k, 1%, 0.125 W, 0805; Manufacturer: Panasonic; CompType: Resistor; Value: 24.9k; Res_ohm: 24900; Value_Code: 24k9; Tolerance_%: 1; Power_W: 0.125; Value2: 0.125W; TempCo: 100 ppm/C; EIA_Code: E96; U/M: EA
R28 = CRCW08054K70JNEA: RES, 4.7 k, 5%, 0.125 W, 0805; Manufacturer: Vishay-Dale; CompType: Resistor; Value: 4.7k; Res_ohm: 4700; Value_Code: 4k70; Tolerance_%: 5; Power_W: 0.125; Value2: 0.125W; VDC_V: 150; TempCo: 200 ppm/C; EIA_Code: E24; U/M: EA
R29 = CRCW08057K68FKEA: as R34 on sheet TIDA-00467_Sheet1
R56 = CRCW060312K0JNEA: RES, 12 k, 5%, 0.1 W, 0603; Manufacturer: Vishay-Dale; CompType: Resistor; Value: 12k; Res_ohm: 12000; Value_Code: 12k0; Tolerance_%: 5; Power_W: 0.1; Value2: 0.1W; VDC_V: 75; TempCo: 200 ppm/C; EIA_Code: E24; U/M: EA
R57 = CRCW0603200RJNEA: RES, 200, 5%, 0.1 W, 0603; Manufacturer: Vishay-Dale; CompType: Resistor; Value: 200; Value_Code: 200R; Tolerance_%: 5; Power_W: 0.1; Value2: 0.1W; VDC_V: 75; TempCo: 200 ppm/C; EIA_Code: E24; U/M: EA
U1 = LM5109AMAX/NOPB: High Voltage 1A Peak Half Bridge Gate Driver, 8-pin Narrow SOIC, Pb-Free; Manufacturer: Texas Instruments; PackageTopMarking: NSZXTT*L5109*AMA; PowerWise: N; CompType: MiscPower
U5 = UCC28880DR: 700-V Lowest Quiescent Current Off-Line Switcher, D0007A; Manufacturer: Texas Instruments; SymbolCreator: a0411947; CompType: IC; U/M: EA

## Sheet Hardware.SchDoc
size 431 x 279 mm; Date: Not shown in title block; ApprovedBy: Not shown in title block; CheckedBy: Not shown in title block; Author: Not shown in title block; CompanyName: Not shown in title block; Engineer: Not shown in title block; Organization: Not shown in title block; Address1: Not shown in title block; Address2: Not shown in title block; Address3: Not shown in title block; Address4: Not shown in title block; DocumentNumber: 1; Revision: Use project parameter SCH_Rev; SheetNumber: 3; SheetTotal: 3; PageSetup: Record=PageOptions¦CenterHorizontal=True¦CenterVertical=True¦PrintScale=0.59¦XCorrection=1.00¦YCorrection=1.00¦PrintKind=0¦BorderSize=5000000¦LeftOffset=0¦BottomOffset=0¦Orientation=2¦PaperLength=1000¦PaperWidth=1000¦Scale=100¦PaperSource=15¦PrintQuality=600¦MediaType=1¦DitherType=10¦PaperKind=Letter¦PrintScaleMode=1
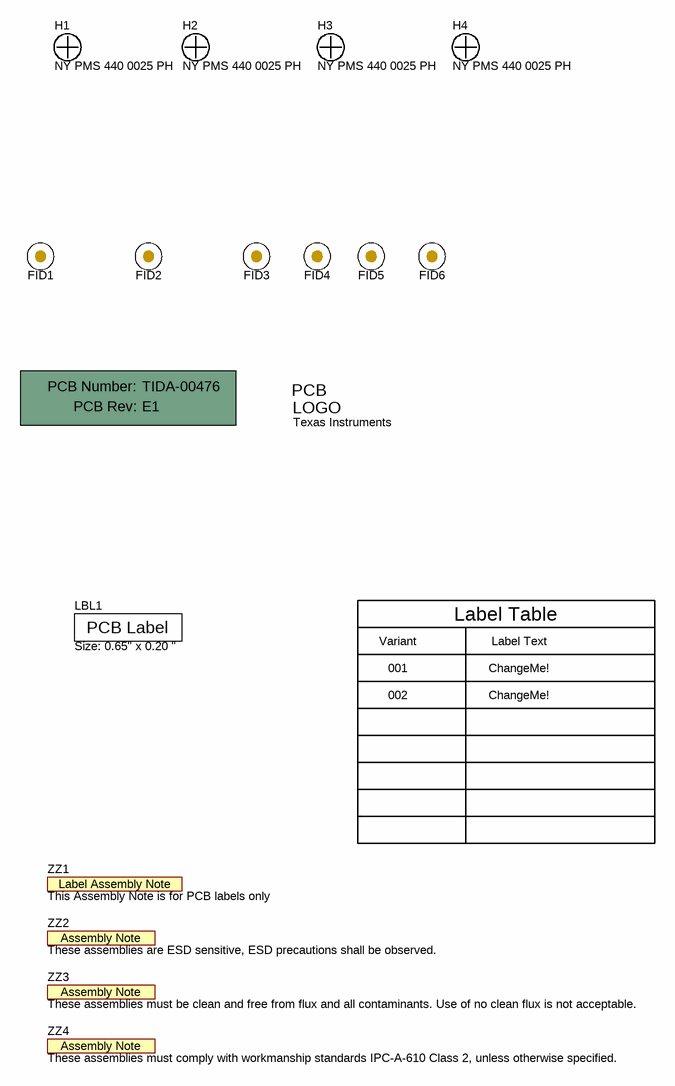
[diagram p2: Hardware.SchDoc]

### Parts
!PCB1  Printed Circuit Board  (value not drawn)  (mechanical)
FID1  Fiducial  [Fiducial10-20]  (value not drawn)
FID2  Fiducial  [Fiducial10-20]  (value not drawn)
FID3  Fiducial  [Fiducial10-20]  (value not drawn)
FID4  Fiducial  [Fiducial10-20]  (value not drawn)
FID5  Fiducial  [Fiducial10-20]  (value not drawn)
FID6  Fiducial  [Fiducial10-20]  (value not drawn)
H1  NY PMS 440 0025 PH  [NY PMS 440 0025 PH]
H2  NY PMS 440 0025 PH  [NY PMS 440 0025 PH]
H3  NY PMS 440 0025 PH  [NY PMS 440 0025 PH]
H4  NY PMS 440 0025 PH  [NY PMS 440 0025 PH]
LBL1  Size: 0.65" x 0.20 "  [Label_650x200]
Logo1  Texas Instruments  [TI_Stacked_Overlay_Small]  (no BOM)
ZZ1  This Assembly Note is for PCB labels only  [AssemblyNoteLabel]  (no BOM)
ZZ2  These assemblies are ESD sensitive, ESD precautions shall be observed.  [AssemblyNote]  (no BOM)
ZZ3  These assemblies must be clean and free from flux and all contaminants. Use of no clean flux is not acceptable.  [AssemblyNote]  (no BOM)
ZZ4  These assemblies must comply with workmanship standards IPC-A-610 Class 2, unless otherwise specified.  [AssemblyNote]  (no BOM)

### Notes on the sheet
- Label Table
- Variant
- 001
- Label Text
- ChangeMe!
- 002

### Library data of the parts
!PCB1 = PCB: Manufacturer: Any; PartNumber: TIDA-00476; SymbolCreator: a0412235
FID1-FID6 = Fiducial: Fiducial mark.  There is nothing to buy or mount.; SymbolCreator: codlsc
H1-H4 = NY PMS 440 0025 PH: Machine Screw, Round, #4-40 x 1/4, Nylon, Philips panhead; Manufacturer: B&F Fastener Supply; CompType: Hardware; SymbolCreator: codlsc; U/M: EA
LBL1 = THT-14-423-10: Thermal Transfer Printable Labels, 0.650" W x 0.200" H - 10,000 per roll; Manufacturer: Brady; SymbolCreator: a0412235; CompType: Label
Logo1 = TI_Logo: Texas Instrument Corporate Signature; SymbolCreator: codlsc
ZZ1 = AssemblyNoteLabel: SymbolCreator: a0412235
ZZ2-ZZ4 = AssemblyNote: SymbolCreator: codlsc

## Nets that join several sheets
GND: TIDA-00467_Sheet1 (23 pins), TIDA-00476_Sheet2 (8 pins)
B-: TIDA-00467_Sheet1 (R51.1), TIDA-00476_Sheet2 (5 pins)
B_S: TIDA-00467_Sheet1 (R54.1), TIDA-00476_Sheet2 (6 pins)
B_V: TIDA-00467_Sheet1 (R35.1), TIDA-00476_Sheet2 (Q7.3 R29.2)
L_EN: TIDA-00467_Sheet1 (R36.1), TIDA-00476_Sheet2 (Q10.1 R30.2)
L_S: TIDA-00467_Sheet1 (R40.1), TIDA-00476_Sheet2 (Q3.3 R11.1 R12.1)
P+: TIDA-00467_Sheet1 (R39.1), TIDA-00476_Sheet2 (18 pins)
P_EN: TIDA-00467_Sheet1 (R34.1), TIDA-00476_Sheet2 (Q8.1 R31.2)
P_V: TIDA-00467_Sheet1 (R33.1), TIDA-00476_Sheet2 (Q6.3 R28.2)
PW_H: TIDA-00467_Sheet1 (R49.1), TIDA-00476_Sheet2 (U1.2)
PW_L: TIDA-00467_Sheet1 (R48.1), TIDA-00476_Sheet2 (C5.1 U1.3)
V+: TIDA-00467_Sheet1 (C18.1 D4.3 U4.5), TIDA-00476_Sheet2 (D2.1 R24.1)
VCC: TIDA-00467_Sheet1 (C19.1 U3.2), TIDA-00476_Sheet2 (11 pins)

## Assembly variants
001: not fitted C5 L3 L4 L5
